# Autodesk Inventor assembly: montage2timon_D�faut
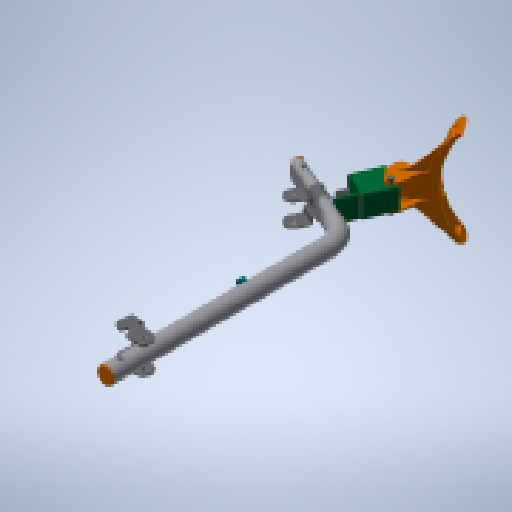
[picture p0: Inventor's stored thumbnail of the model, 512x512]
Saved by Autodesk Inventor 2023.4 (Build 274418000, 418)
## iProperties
Created: 2011-01
Part Number: montage2timon_D�faut
Document SubType Name: Assembly
Designer: eric
Mass: 224.141 g
Surface Area: 2423.2 cm^2
Volume: 224.141 cm^3
Density: 1 g/cm^3
Author: eric
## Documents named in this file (17)
- C:\Users\bruno\Documents\1-Cours-2024-25\TSsI\7-Dynamique\chariot de golf\chariot_de_golf\chariot_de_golf_trolem\montage2timon_Defaut.iam
- C:\Users\bruno\Documents\1-Cours-2024-25\TSsI\7-Dynamique\chariot de golf\chariot_de_golf\chariot_de_golf_trolem\31verrou_bas_Defaut.ipt
- C:\Users\bruno\Documents\1-Cours-2024-25\TSsI\7-Dynamique\chariot de golf\chariot_de_golf\chariot_de_golf_trolem\58embout_ovale_Defaut.ipt
- C:\Users\bruno\Documents\1-Cours-2024-25\TSsI\7-Dynamique\chariot de golf\chariot_de_golf\chariot_de_golf_trolem\bead60_Defaut.ipt
- C:\Users\bruno\Documents\1-Cours-2024-25\TSsI\7-Dynamique\chariot de golf\chariot_de_golf\chariot_de_golf_trolem\35Vis_CBLZ_M6_55.ipt
- C:\Users\bruno\Documents\1-Cours-2024-25\TSsI\7-Dynamique\chariot de golf\chariot_de_golf\chariot_de_golf_trolem\bead50_Defaut.ipt
- C:\Users\bruno\Documents\1-Cours-2024-25\TSsI\7-Dynamique\chariot de golf\chariot_de_golf\chariot_de_golf_trolem\bead51_Defaut.ipt
- C:\Users\bruno\Documents\1-Cours-2024-25\TSsI\7-Dynamique\chariot de golf\chariot_de_golf\chariot_de_golf_trolem\bead61_Defaut.ipt
- C:\Users\bruno\Documents\1-Cours-2024-25\TSsI\7-Dynamique\chariot de golf\chariot_de_golf\chariot_de_golf_trolem\bead52_Defaut.ipt
- C:\Users\bruno\Documents\1-Cours-2024-25\TSsI\7-Dynamique\chariot de golf\chariot_de_golf\chariot_de_golf_trolem\34support_avant_Defaut.ipt
- C:\Users\bruno\Documents\1-Cours-2024-25\TSsI\7-Dynamique\chariot de golf\chariot_de_golf\chariot_de_golf_trolem\2chappe_Defaut.ipt
- C:\Users\bruno\Documents\1-Cours-2024-25\TSsI\7-Dynamique\chariot de golf\chariot_de_golf\chariot_de_golf_trolem\2timon_Defaut.iam
- C:\Users\bruno\Documents\1-Cours-2024-25\TSsI\7-Dynamique\chariot de golf\chariot_de_golf\chariot_de_golf_trolem\bead53_Defaut.ipt
- C:\Users\bruno\Documents\1-Cours-2024-25\TSsI\7-Dynamique\chariot de golf\chariot_de_golf\chariot_de_golf_trolem\1carre_assemble_Defaut.iam
- C:\Users\bruno\Documents\1-Cours-2024-25\TSsI\7-Dynamique\chariot de golf\chariot_de_golf\chariot_de_golf_trolem\45bouchon_cylindrique_Defaut.ipt
- C:\Users\bruno\Documents\1-Cours-2024-25\TSsI\7-Dynamique\chariot de golf\chariot_de_golf\chariot_de_golf_trolem\53guide_cable_Defaut.ipt
- C:\Users\bruno\Documents\1-Cours-2024-25\TSsI\7-Dynamique\chariot de golf\chariot_de_golf\chariot_de_golf_trolem\36Ecrou H_ FR_ M6.ipt
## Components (16 placed, 16 different names)
1. 31verrou_bas_Defaut:1
2. 58embout_ovale_Defaut:1
3. bead60_Defaut:1
4. 35Vis_CBLZ_M6_55:1 — Logement:3
5. bead50_Defaut:1
6. bead51_Defaut:1
7. bead61_Defaut:1
8. bead52_Defaut:1
9. 34support_avant_Defaut:1 — Logement:1, Logement:2, Logement:3
10. 2chappe_Defaut:1
11. 2timon_Defaut:1 [sub-assembly]
12. bead53_Defaut:1
13. 1carre_assemble_Defaut:1 [sub-assembly] — Logement:1
14. 45bouchon_cylindrique_Defaut:1
15. 53guide_cable_Defaut:1
16. 36Ecrou H_ FR_ M6:1 — Logement:2
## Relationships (3: Insert 3)
- Logement:1 [Insert]: 34support_avant_Defaut:1 ↔ 1carre_assemble_Defaut:1
- Logement:2 [Insert]: 34support_avant_Defaut:1 ↔ 36Ecrou H_ FR_ M6:1
- Logement:3 [Insert]: 35Vis_CBLZ_M6_55:1 ↔ 34support_avant_Defaut:1
